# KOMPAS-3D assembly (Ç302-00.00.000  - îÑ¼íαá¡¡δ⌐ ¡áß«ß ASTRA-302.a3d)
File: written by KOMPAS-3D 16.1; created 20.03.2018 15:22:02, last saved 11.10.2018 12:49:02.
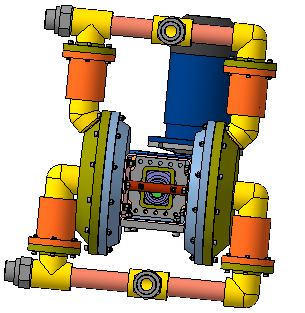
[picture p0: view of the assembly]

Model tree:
1. Массив по образцу:1  (12 pattern instances)
2. Сечение поверхностью:1
3. Сечение поверхностью:3
4. Сечение поверхностью:2  (labels: А302-00.00.000; C:\Program Files\ASCON\KOMPAS-3D V16\Sys\bo_atr.lat; А302-00.00.000)
     Расстояние = -0.5; Расстояние = -0.5

Expressions: A2-70; М6 x 50 - A2-70
Referenced files in Z:\Мембранные насосы\Мембранный электропривод\А302-00.00.000 - ASTRA-302 (МЭ200)\3Д\: А302-00.05.000 - Корпус.a3d, А302-00.15.001 - Мембрана.a3d, А302-00.10.000 - Рабочая камера.a3d
Referenced files in C:\Program Files\ASCON\KOMPAS-3D V16\Libs\PartLib\DATA\vault\Methods\Kompas\3D\: PLib_Washer_1_712.m3d, PLib_Screw_DIN_7984_1500.m3d
Referenced files in Z:\1 ПКИ 3D\Полипропиленовые фитинги, трубы\: Колено 90гр 40 FV PPR ф. FV PLAST.m3d, Тройник 40 FV PPR ф. FV PLAST.m3d, Переходник с пластмассовой резьбой наружной 40х1 1_4 FV PPR ф.FV Plast.m3d
Referenced files in Z:\1 ПКИ 3D\Полипропиленовые фитинги, трубы\Трубы\: Труба 40 PN10 S=3,7 FV PPR ф. FV PLAST.m3d
Referenced files in C:\Program Files\ASCON\KOMPAS-3D V16\Libs\PartLib\DATA\VAULT\Methods\kompas\3d\: PLib_Washer_2_712.m3d
Referenced files in Z:\2 Стандартные изделия 3D\Гайки\DIN 6927\: Гайка шестигранная самостопорящаяся с фланцем DIN 6927-M6 - A2-70.m3d
Referenced files in Z:\Мембранные насосы\Мембранный электропривод\А302-00.00.000 - ASTRA-302 (МЭ200)\Чертежи\: А302-00.05.000 - Корпус.cdw, А302-00.10.000 - Рабочая камера.cdw
Referenced files: graphic.tdp
Referenced files in \\192.168.87.28\Konstructor_doc\Мембранные насосы\Мембранный электропривод\А302-00.00.000 - ASTRA-302 (МЭ200)\Чертежи\: А302-00.15.000 - Мембрана.cdw
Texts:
  (ф) А302-00.05.000 Корпус
  (-) А302-00.15.000 Мембрана (1)
  (-) А302-00.15.000 Мембрана (2)
  Сталь 20 ГОСТ 1050-2013
  Шайба C 12.04.019 ГОСТ 6958-78
  Крепежное изделие ГОСТ
  (-) Шайба C 12.04.019 ГОСТ 6958-78 (1)
  (-) Шайба C 12.04.019 ГОСТ 6958-78 (2)
  (-) А302-00.10.000 Рабочая камера (1)
  (-) А302-00.10.000 Рабочая камера (2)
  Колено 90@1~ @2~40 FV PPR ф. "FV PLAST"
  (-) Колено 90гр 40 FV PPR ф. FV PLAST (1)
  Тройник @2~40 FV PPR ф. "FV PLAST"
  (-) Тройник 40 FV PPR ф. FV PLAST (1)
  (-) Тройник 40 FV PPR ф. FV PLAST (2)
  (-) Колено 90гр 40 FV PPR ф. FV PLAST (2)
  (-) Тройник 40 FV PPR ф. FV PLAST (3)
  (-) Тройник 40 FV PPR ф. FV PLAST (4)
  Труба 40 PN10 S=3,7 FV PPR ф. FV PLAST
  (-) Труба ф40х3,7 (PN10) FV PPR ф. FV PLAST (1)
  (-) Труба ф40х3,7 (PN10) FV PPR ф. FV PLAST (2)
  Переходник с пластмассовой резьбой
  наружной 40х1 1/4" FV PPR
  ф. "FV PLAST"
  Переходник с пластмассовой резьбой  / наружной 40х1 1/4" FV PPR  / ф. "FV PLAST"
  (-) Переходник с пластмассовой резьбой наружной 40х1 1/4" FV PPR ф."FV Plast" (1)
  (-) Труба ф40х3,7 (PN10) FV PPR ф. FV PLAST (3)
  (-) Труба ф40х3,7 (PN10) FV PPR ф. FV PLAST (4)
  (-) Переходник с пластмассовой резьбой наружной 40х1 1/4" FV PPR ф."FV Plast" (2)
  (-) Переходник с пластмассовой резьбой наружной 40х1 1/4" FV PPR ф."FV Plast" (3)
  (-) Переходник с пластмассовой резьбой наружной 40х1 1/4" FV PPR ф."FV Plast" (4)
  Сталь 12Х18Н10Т ГОСТ 5632-72
  Шайба C.6.21 ГОСТ 11371-78
  (-) Шайба C.6.21 ГОСТ 11371-78 (1)
  Сталь 30Х13 ГОСТ 5632-72
  Шайба 6 30Х13 019 ГОСТ 6402-70
  (-) Шайба 6 30Х13 019 ГОСТ 6402-70 (1)
  Винт с цилиндрической головкой и шестигранным углублением под ключ ГОСТ Р ИСО 4762 - М6 x 50 - A2-70
  Винт с цилиндрической головкой
  и шестигранным углублением под ключ
  ГОСТ Р ИСО  4762-М6 x 50-A2-70
  Винт с цилиндрической головкой и шестигранным углублением под ключ
  (-) Винт с цилиндрической головкой и шестигранным углублением под ключ ГОСТ Р ИСО 4762 - М6 x 50 - A2-70 (1)
  Гайка шестигранная самостопорящаяся с фланцем
  DIN 6927-M6 - A2-70
  (-) Гайка шестигранная самостопорящаяся с фланцем DIN 6927-M6 - A2-70 (1)
  (-) Гайка шестигранная самостопорящаяся с фланцем DIN 6927-M6 - A2-70 (2)
  (-) Шайба C.6.21 ГОСТ 11371-78 (2)
  (-) Шайба 6 30Х13 019 ГОСТ 6402-70 (2)
  Винт с цилиндрической головкой и шестигранным углублением под ключ ГОСТ Р ИСО  4762-М6 x 50-A2-70
  (-) Винт с цилиндрической головкой и шестигранным углублением под ключ ГОСТ Р ИСО 4762 - М6 x 50 - A2-70 (2)
  (-) Шайба C.6.21 ГОСТ 11371-78 (3)
  (-) Шайба 6 30Х13 019 ГОСТ 6402-70 (3)
  (-) Винт с цилиндрической головкой и шестигранным углублением под ключ ГОСТ Р ИСО 4762 - М6 x 50 - A2-70 (3)
  (-) Гайка шестигранная самостопорящаяся с фланцем DIN 6927-M6 - A2-70 (14)
  Мембранный насос ASTRA-302
  ГОСТ 6958-78
  ГОСТ 11371-78
  ГОСТ 6402-70
  ГОСТ Р ИСО 4762-2012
